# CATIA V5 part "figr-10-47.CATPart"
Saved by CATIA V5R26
Part number: Part1
Bounding box of the stored display mesh (mm): x 0 to 149.165, y -56.328 to 246, z -79.956 to 99.365
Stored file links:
  D:\_Deepak\CATIA\CATIA V5-6R2016_Deepak\Resources\Part files\Partfiles\c10_catia_v5_6r2016_prt\figr-10-47.CATPart
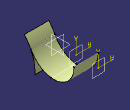
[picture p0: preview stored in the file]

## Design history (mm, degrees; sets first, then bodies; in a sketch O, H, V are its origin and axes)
Body1 (main body)
  Sketch1 on yz-plane, origin (0, 0, 0), H (0, 1, 0), V (0, 0, 1)
    arc A1 centre (-231.2925, -65.467) radius 240.3792 from (-56.3278, 99.3648) to (8.6496, -79.9559) cw
    coincidence: A1 O
  Extrude1: Element1 Sketch1, Lim1 149, Lim2 0
  Sketch2 on zx-plane, origin (0, 0, 0), H (-1, 0, 0), V (0, 0, 1)
    line L1 (-147.95, 52.1519) -> (0, 52.1519)
    point P1 (0, 52.1519)
    coincidence: P1 V
    horizontal: L1 H
  Project1: ToProject Sketch2, Support Extrude1
  Plane1: type Offset, RefPlane zx-plane, Offset 110
  Plane2: type Offset, RefPlane Plane1, Offset 136
  Sketch3 on Plane1, origin (0, 110, 0), H (-1, 0, 0), V (0, 0, 1)
    line L1 (-149.1647, -46.834) -> (0, -46.834)
    point P1 (0, -46.834)
    coincidence: P1 V
    horizontal: L1 H
  Sketch4 on Plane2, origin (0, 246, 0), H (-1, 0, 0), V (0, 0, 1)
    line L1 (-148.4227, 79.0713) -> (0, 79.0713)
    point P1 (0, 79.0713)
    coincidence: P1 V
    horizontal: L1 H
  Sweep1: type Conic, Guide ({sweepconicextendedguide Guide Project1, Reference Extrude1, Angle 0}; Sketch3; {sweepconicextendedguide Guide Sketch4, Reference Plane2, Angle 0})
